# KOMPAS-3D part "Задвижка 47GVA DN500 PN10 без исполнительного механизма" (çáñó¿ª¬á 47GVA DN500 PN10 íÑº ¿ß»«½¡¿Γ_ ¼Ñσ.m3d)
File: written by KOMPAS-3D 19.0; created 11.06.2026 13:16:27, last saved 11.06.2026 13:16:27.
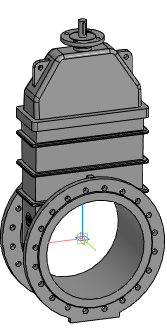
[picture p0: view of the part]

Document properties: Автор: Евгений; Полное имя файла: Z:\3.Личные\kachalov\001_3d для проектировщиков\2.2 Тип 47GVA, 47GVA.Z\_stp\_stp_Задвижка 47GVA DN40-DN1000 без исп.мех\Задвижка 47GVA DN500 PN10 без исполнит_ мех.m3d

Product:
- Part/product: Задвижка 47GVA DN500 PN10 без исполнительного механизма

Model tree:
1. Операция без истории:1  (labels: Задвижка 47GVA DN500 PN10 без исполнительного механизма)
